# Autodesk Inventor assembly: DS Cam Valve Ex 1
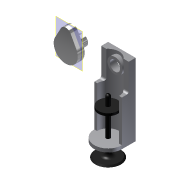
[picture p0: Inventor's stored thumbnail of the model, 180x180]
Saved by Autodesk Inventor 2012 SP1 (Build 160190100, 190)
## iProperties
Created: 2006-03
Part Number: DS Cam Valve Ex 1
Document SubType Name: Assembly
Designer: debonom
Mass: 106.077 g
Surface Area: 257.233 cm^2
Volume: 63.3349 cm^3
Density: 1.67485 g/cm^3
Author: debonom
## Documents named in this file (4)
- D:\Backup\CMU Work\CamValve.iam
- D:\Backup\CMU Work\Support.ipt
- D:\Backup\CMU Work\Valve.ipt
- D:\Backup\CMU Work\Cam.ipt
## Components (3 placed, 3 different names)
1. Support:1
2. Valve:1
3. Cam:1
